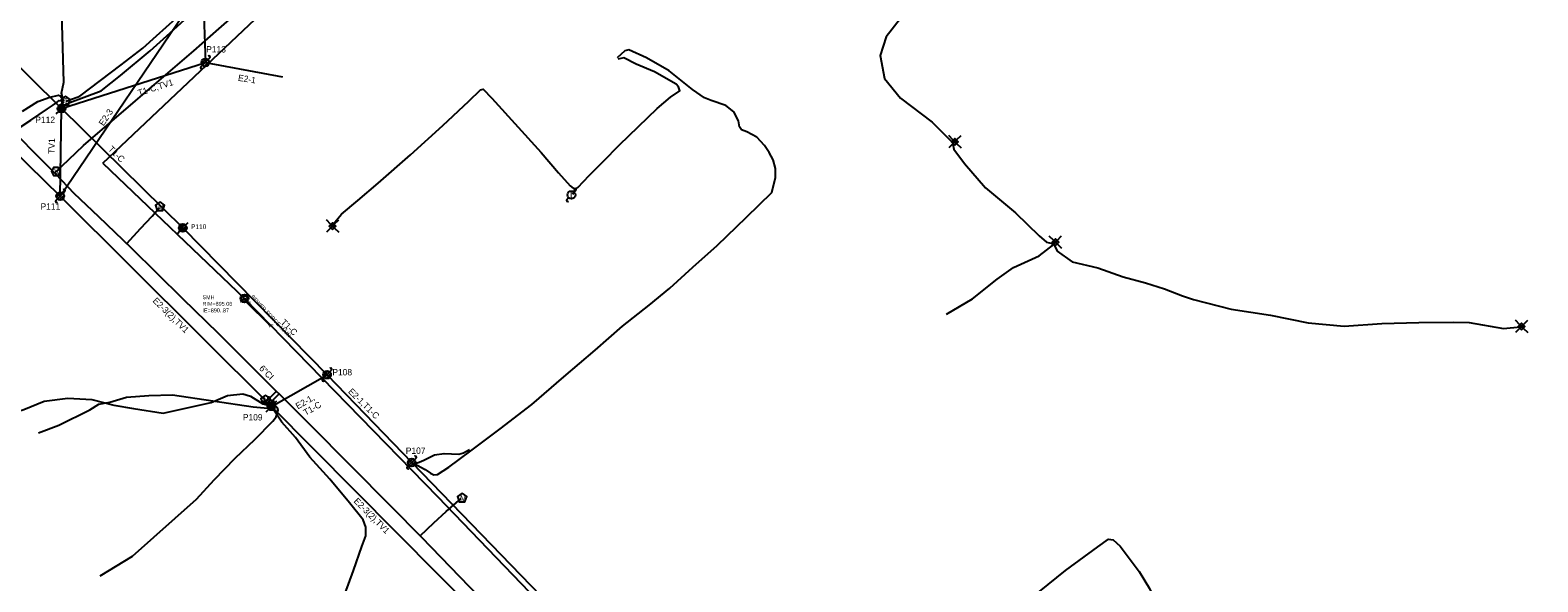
# Model space of a CAD drawing. Extents: x 1614474 to 1865144, y 1098877 to 1212550.
# Drawn here: x 1755426 to 1756381, y 1170044 to 1170393 of the extents above; entities that cross this region are included whole.
import ezdxf

# ---------------------------------------------------------------- set-up
doc = ezdxf.new("R2010")
doc.units = 0
for name, color, linetype in [('Default', 7, 'Continuous'), ('RD_EX_SU_Elec', 7, 'Continuous'), ('RD_EX_SU_H2O', 7, 'Continuous'), ('RD_EX_SU_Ovhd', 7, 'Continuous'), ('RD_EX_SU_Pole', 7, 'Continuous'), ('RD_EX_SU_Sewer', 7, 'Continuous'), ('RD_EX_SU_Telecom', 7, 'Continuous'), ('RD_EX_SU_TX_H2O', 7, 'Continuous'), ('RD_EX_SU_TX_Pole', 7, 'Continuous'), ('RD_EX_SU_TX_Sewer', 7, 'Continuous'), ('RD_EX_UT_txCode', 7, 'Continuous'), ('RD_SMD_Locator', 7, 'Continuous')]:
    doc.layers.add(name, color=color, linetype=linetype)

# ---------------------------------------------------------------- blocks, each defined once
blk = doc.blocks.new('SUE_PTP')
at = {"layer": 'RD_EX_SU_Pole'}
for p, q in [((-2.48, -0.33), (0.33, 2.48)), ((-2.1, -1.36), (1.36, 2.1)), ((-1.4, -2.08), (2.08, 1.4)), ((-0.38, -2.47), (2.47, 0.38)), ((1.77, 1.77), (3.42, 3.42)), ((-3.42, -3.42), (-1.77, -1.77)), ((1.52, -1.99), (1.99, -1.52))]:
    blk.add_line(p, q, dxfattribs=at)
blk.add_circle((0, 0), 2.5, dxfattribs=at)
blk = doc.blocks.new('SUE_SMH')
at = {"layer": 'RD_EX_SU_Sewer'}
blk.add_circle((0, 0), 2.5, dxfattribs=at)
blk.add_text('S', height=3.57, dxfattribs=at).set_placement((-1.1, -1.79))

msp = doc.modelspace()

# ---------------------------------------------------------------- linework, layer by layer
at = {"layer": 'Default'}
for p, q in [((1755562.03, 1170222.49), (1755560.63, 1170222.49)), ((1755561.33, 1170223.19), (1755561.33, 1170221.79))]:
    msp.add_line(p, q, dxfattribs=at)
at = {"layer": 'RD_EX_SU_Elec'}
msp.add_line((1755769.73, 1170288.79), (1755771.94, 1170292.51), dxfattribs=at)
for points in [[(1756017.8, 1170428.16), (1756008.58, 1170424.13), (1755977.33, 1170399.9), (1755968.08, 1170388.43), (1755964.43, 1170376.64), (1755967.1, 1170361.97), (1755977.19, 1170349.66), (1755997.36, 1170334.46), (1756009.95, 1170321.75)], [(1755669.02, 1170118.78), (1755676.38, 1170114.79), (1755679.78, 1170112.45), (1755681.75, 1170111.48), (1755684.09, 1170111.64), (1755691.34, 1170116.24), (1755705.15, 1170126.55), (1755723.71, 1170140.58), (1755743.76, 1170155.96), (1755764.15, 1170173.48), (1755783.87, 1170190.32), (1755801.35, 1170205.51), (1755818.14, 1170218.73), (1755831.29, 1170229.36), (1755845.85, 1170242.71), (1755861.2, 1170256.39), (1755879.67, 1170274.4), (1755895.87, 1170290.03), (1755898.13, 1170299.43), (1755898.05, 1170305.12), (1755896.64, 1170310.54), (1755894.02, 1170315.33), (1755891.25, 1170319.72), (1755886.27, 1170324.96), (1755879.88, 1170328.25), (1755876.6, 1170329.65), (1755875.38, 1170331.44), (1755874.71, 1170335.3), (1755871.77, 1170340.94), (1755866.63, 1170344.91), (1755857.41, 1170348.16), (1755853.09, 1170349.71), (1755845.62, 1170355.02), (1755830.83, 1170366.84), (1755816.52, 1170375.19), (1755805.26, 1170380.24), (1755802.74, 1170379.53), (1755797.92, 1170375.06)], [(1755618.1, 1170269.96), (1755623.39, 1170276.22), (1755633.75, 1170284.81), (1755646.57, 1170295.84), (1755666.96, 1170313.82), (1755687.48, 1170332.23), (1755703.98, 1170347.72), (1755711.25, 1170354.85), (1755713.07, 1170355.19), (1755718.51, 1170349.68), (1755749.77, 1170315.15), (1755760.69, 1170302.36), (1755768.14, 1170294.21), (1755770.98, 1170291.84), (1755772.95, 1170293.2), (1755780.25, 1170300.69), (1755789.11, 1170309.46), (1755799.38, 1170320.09), (1755823.12, 1170343.14), (1755831.66, 1170350.19), (1755837.58, 1170354.28), (1755836.65, 1170356.73), (1755835.13, 1170358.52), (1755821.44, 1170366.22), (1755809.99, 1170371.15), (1755802.05, 1170375.1), (1755798.27, 1170374.17)], [(1756010.36, 1170320.8), (1756011.01, 1170317.24), (1756017.76, 1170308.34), (1756030.98, 1170292.91), (1756050.1, 1170277.01), (1756065.02, 1170262.49), (1756069.77, 1170258.45), (1756073.45, 1170257.78)], [(1756006.39, 1170213.05), (1756022.78, 1170222.76), (1756038.42, 1170235.07), (1756048.77, 1170242.48), (1756065.02, 1170249.8), (1756074.27, 1170257.02)], [(1756074.51, 1170256.77), (1756076.39, 1170252.9), (1756085.89, 1170246.13), (1756102.17, 1170242.39), (1756118.29, 1170236.61), (1756132.4, 1170232.92), (1756144.33, 1170229.04), (1756155.71, 1170224.63), (1756162.64, 1170222.23), (1756186.51, 1170216.21), (1756211.5, 1170212.34), (1756235.26, 1170207.54), (1756258.17, 1170205.47), (1756281.96, 1170207.21), (1756305.43, 1170207.68), (1756327.12, 1170208.01), (1756337.21, 1170207.77), (1756359.06, 1170203.86), (1756369.7, 1170205.08)], [(1755431.62, 1170137.94), (1755444.3, 1170142.89), (1755464.09, 1170152.6), (1755469.74, 1170156.01), (1755476.6, 1170157.29), (1755487.21, 1170160.47), (1755501.41, 1170161.58), (1755516.41, 1170161.91), (1755567.36, 1170154.34), (1755576.72, 1170153.67), (1755579.12, 1170153.23)], [(1756022.72, 1169998.91), (1756038.36, 1170014.52), (1756054.32, 1170028.79), (1756081.79, 1170050.93), (1756102.19, 1170065.98), (1756109.03, 1170070.78), (1756111.93, 1170070.43), (1756116.38, 1170066.35), (1756128.3, 1170050.38), (1756134.86, 1170039.55), (1756137.29, 1170034.72), (1756139.43, 1170030.67), (1756144.81, 1170015.47), (1756151.96, 1169991.44), (1756159.74, 1169966.17), (1756168.64, 1169940.65), (1756178.37, 1169914.6), (1756188.01, 1169891.65), (1756198.92, 1169863.88), (1756203.62, 1169854.78), (1756207.42, 1169842.53)]]:
    msp.add_lwpolyline(points, dxfattribs=at)
at = {"layer": 'RD_EX_SU_H2O'}
for p, q in [((1755575.81, 1170158.11), (1755582.18, 1170164.3)), ((1755576.79, 1170160.62), (1755576.79, 1170159.29)), ((1755577.84, 1170160.62), (1755576.79, 1170160.62)), ((1755577.84, 1170159.26), (1755577.84, 1170160.62)), ((1755578.48, 1170157.26), (1755583.92, 1170162.62)), ((1755575.25, 1170157.84), (1755573.62, 1170157.84)), ((1755573.62, 1170157.84), (1755573.62, 1170156.79)), ((1755573.62, 1170156.79), (1755575.21, 1170156.79)), ((1755580.97, 1170157.84), (1755579.28, 1170157.84)), ((1755579.32, 1170156.79), (1755580.97, 1170156.79)), ((1755580.97, 1170156.79), (1755580.97, 1170157.84))]:
    msp.add_line(p, q, dxfattribs=at)
for points in [[(1755441.66, 1170302.24), (1755460.1, 1170319.63), (1755492.98, 1170347.81), (1755529.94, 1170379.56), (1755545.71, 1170393.41), (1755580.96, 1170424.36), (1755625.65, 1170470.71), (1755664.97, 1170520.56), (1755702.01, 1170579.47), (1755735.13, 1170631.62), (1755761.05, 1170675.7), (1755767.99, 1170686.69), (1755768.97, 1170688.48), (1755794.48, 1170732.14), (1755816.54, 1170772.41), (1755845.31, 1170822.63), (1755906.99, 1170918.56)], [(1755419.51, 1170324.82), (1755428.9, 1170315.01), (1755440.94, 1170302.99), (1755442.22, 1170301.65), (1755453.83, 1170289.61), (1755469.55, 1170274.72), (1755490.11, 1170254.98), (1755522.61, 1170222.9), (1755545.21, 1170201.07), (1755581.64, 1170164.83), (1755584.47, 1170162.08), (1755603.36, 1170143.23), (1755654.48, 1170091.61), (1755673.95, 1170071.98), (1755722.41, 1170022.15)], [(1755487.36, 1170257.63), (1755496.08, 1170267.09), (1755503.52, 1170274.97), (1755508.06, 1170280.36)], [(1755673.06, 1170072.88), (1755681.7, 1170080.98), (1755689.61, 1170088.29), (1755699.1, 1170096.4)]]:
    msp.add_lwpolyline(points, dxfattribs=at)
for points in [[(1755445.45, 1170303.25), (1755444.01, 1170305.75), (1755441.12, 1170305.75), (1755439.68, 1170303.25), (1755441.12, 1170300.75), (1755444.01, 1170300.75)], [(1755508.49, 1170284.08), (1755505.59, 1170281.98), (1755506.7, 1170278.57), (1755510.29, 1170278.57), (1755511.39, 1170281.98)], [(1755575.27, 1170161.77), (1755572.37, 1170159.67), (1755573.47, 1170156.26), (1755577.06, 1170156.26), (1755578.17, 1170159.67)], [(1755699.72, 1170099.88), (1755696.82, 1170097.78), (1755697.93, 1170094.37), (1755701.51, 1170094.37), (1755702.62, 1170097.78)]]:
    msp.add_lwpolyline(points, close=True, dxfattribs=at)
for radius in [2.1, 0.263]:
    msp.add_circle((1755577.27, 1170157.24), radius, dxfattribs=at)
for start, end in [(163.3387, 192.31502), (74.24552, 103.21276), (347.68498, 16.6613)]:
    msp.add_arc((1755577.27, 1170157.24), 2.1, start, end, dxfattribs=at)
at = {"layer": 'RD_EX_SU_Ovhd'}
for p, q in [((1755346.94, 1170440.97), (1755446.08, 1170343.01)), ((1755445.31, 1170287.7), (1755535.55, 1170420.8)), ((1755535.55, 1170420.8), (1755537.22, 1170372.19)), ((1755341.33, 1170388.64), (1755445.31, 1170287.7)), ((1755446.08, 1170343.01), (1755537.22, 1170372.19)), ((1755537.22, 1170372.19), (1755585.97, 1170363.18)), ((1755445.31, 1170287.7), (1755446.08, 1170343.01)), ((1755446.08, 1170343.01), (1755522.86, 1170267.55)), ((1755445.31, 1170287.7), (1755579.05, 1170154.72)), ((1755522.86, 1170267.55), (1755614.2, 1170174.75)), ((1755579.05, 1170154.72), (1755614.2, 1170174.75)), ((1755614.2, 1170174.75), (1755667.78, 1170119.23)), ((1755579.05, 1170154.72), (1755733.5, 1169999.29)), ((1755667.78, 1170119.23), (1755866.5, 1169914.45))]:
    msp.add_line(p, q, dxfattribs=at)
at = {"layer": 'RD_EX_SU_Pole'}
for p, q in [((1755534.39, 1170369.36), (1755535.45, 1170370.42)), ((1755534.81, 1170371.54), (1755537.87, 1170374.6)), ((1755535.45, 1170370.42), (1755538.99, 1170373.95)), ((1755536.57, 1170369.77), (1755539.64, 1170372.83)), ((1755538.99, 1170373.95), (1755540.05, 1170375.01)), ((1756010.66, 1170323.11), (1756007.83, 1170325.93)), ((1756012.75, 1170323.16), (1756015.59, 1170326)), ((1756010.61, 1170321), (1756007.78, 1170318.17)), ((1756012.78, 1170320.98), (1756015.61, 1170318.16)), ((1755442.48, 1170284.87), (1755443.54, 1170285.93)), ((1755442.89, 1170287.05), (1755445.96, 1170290.12)), ((1755443.54, 1170285.93), (1755447.08, 1170289.47)), ((1755444.66, 1170285.29), (1755447.72, 1170288.35)), ((1755447.08, 1170289.47), (1755448.14, 1170290.53)), ((1755766.08, 1170285.56), (1755767.14, 1170286.62)), ((1755770.68, 1170290.16), (1755771.74, 1170291.22)), ((1755519.44, 1170264.12), (1755521.1, 1170265.78)), ((1755520.38, 1170267.22), (1755523.2, 1170270.03)), ((1755520.77, 1170266.18), (1755524.23, 1170269.64)), ((1755521.47, 1170265.47), (1755524.94, 1170268.94)), ((1755522.49, 1170265.07), (1755525.34, 1170267.93)), ((1755524.39, 1170265.56), (1755524.85, 1170266.02)), ((1755524.63, 1170269.32), (1755526.29, 1170270.97)), ((1755616.59, 1170267.69), (1755613.76, 1170264.87)), ((1755616.64, 1170269.8), (1755613.81, 1170272.63)), ((1755618.72, 1170269.86), (1755621.56, 1170272.7)), ((1755618.76, 1170267.68), (1755621.59, 1170264.85)), ((1756074.19, 1170257.51), (1756071.37, 1170254.68)), ((1756074.24, 1170259.61), (1756071.42, 1170262.44)), ((1756076.33, 1170259.67), (1756079.17, 1170262.51)), ((1756076.37, 1170257.49), (1756079.19, 1170254.66)), ((1756369.43, 1170206.3), (1756366.6, 1170209.13)), ((1756371.51, 1170206.36), (1756374.35, 1170209.2)), ((1756369.37, 1170204.19), (1756366.55, 1170201.37)), ((1756371.55, 1170204.18), (1756374.37, 1170201.35)), ((1755611.37, 1170171.92), (1755612.43, 1170172.98)), ((1755611.79, 1170174.11), (1755614.85, 1170177.17)), ((1755612.43, 1170172.98), (1755615.97, 1170176.52)), ((1755613.56, 1170172.34), (1755616.62, 1170175.4)), ((1755615.97, 1170176.52), (1755617.03, 1170177.58)), ((1755669.55, 1170121), (1755670.61, 1170122.06)), ((1755664.95, 1170116.4), (1755666.01, 1170117.46)), ((1755665.36, 1170118.58), (1755668.43, 1170121.64)), ((1755666.01, 1170117.46), (1755669.55, 1170121)), ((1755667.13, 1170116.81), (1755670.19, 1170119.88))]:
    msp.add_line(p, q, dxfattribs=at)
for points in [[(1756011.72, 1170319.92), (1756013.84, 1170322.04), (1756011.72, 1170324.17), (1756009.6, 1170322.04)], [(1756011.72, 1170321.34), (1756012.43, 1170322.04), (1756011.72, 1170322.75), (1756011.02, 1170322.04)], [(1755617.7, 1170266.62), (1755619.82, 1170268.74), (1755617.7, 1170270.86), (1755615.58, 1170268.74)], [(1755617.7, 1170268.03), (1755618.41, 1170268.74), (1755617.7, 1170269.45), (1755616.99, 1170268.74)], [(1756075.31, 1170256.43), (1756077.43, 1170258.55), (1756075.31, 1170260.67), (1756073.18, 1170258.55)], [(1756075.31, 1170257.85), (1756076.01, 1170258.55), (1756075.31, 1170259.26), (1756074.6, 1170258.55)], [(1756370.49, 1170203.12), (1756372.61, 1170205.24), (1756370.49, 1170207.36), (1756368.36, 1170205.24)], [(1756370.49, 1170204.53), (1756371.19, 1170205.24), (1756370.49, 1170205.95), (1756369.78, 1170205.24)]]:
    msp.add_lwpolyline(points, close=True, dxfattribs=at)
for centre in [(1755537.22, 1170372.19), (1755445.31, 1170287.7), (1755768.91, 1170288.39), (1755522.86, 1170267.55), (1755614.2, 1170174.75), (1755667.78, 1170119.23)]:
    msp.add_circle(centre, 2.5, dxfattribs=at)
for centre, start, end in [((1755539.52, 1170375.54), 315, 135), ((1755534.92, 1170368.83), 135, 315), ((1755443.01, 1170284.34), 135, 315), ((1755447.61, 1170291.06), 315, 135), ((1755766.61, 1170285.03), 135, 315), ((1755771.21, 1170291.75), 315, 135), ((1755611.9, 1170171.39), 135, 315), ((1755616.5, 1170178.11), 315, 135), ((1755670.08, 1170122.59), 315, 135), ((1755665.48, 1170115.87), 135, 315)]:
    msp.add_arc(centre, 0.75, start, end, dxfattribs=at)
at = {"layer": 'RD_EX_SU_Sewer'}
msp.add_line((1755562.64, 1170221.23), (1755578.32, 1170205.72), dxfattribs=at)
for points in [[(1755472.28, 1170308.43), (1755611.28, 1170440.07), (1755685.92, 1170532.6), (1755771.11, 1170666.36), (1755900.75, 1170895.13), (1755970.93, 1170995.72), (1756034.36, 1171088.88), (1756090.2, 1171167.02), (1756147.55, 1171225.76), (1756231.9, 1171306.77), (1756311.52, 1171366.34), (1756443.61, 1171443.81), (1756596.95, 1171527.35), (1756716.89, 1171571.4), (1756861.63, 1171600.26), (1756930.46, 1171628.36), (1757060.01, 1171710.39), (1757108.59, 1171767.1), (1757159.2, 1171859.25), (1757206.77, 1171953.42), (1757250.3, 1172017.89), (1757282.69, 1172067.18)], [(1755472.28, 1170308.43), (1755562.01, 1170223), (1755684.15, 1170097.75), (1755848.2, 1169927.49), (1755891.42, 1169870.58), (1755920.4, 1169827.47), (1756045.49, 1169608.65)]]:
    msp.add_lwpolyline(points, dxfattribs=at)
msp.add_circle((1755561.8, 1170222.9), 2, dxfattribs=at)
at = {"layer": 'RD_EX_SU_Telecom'}
for p, q in [((1755443.6, 1170342.68), (1755446.41, 1170345.49)), ((1755443.99, 1170341.65), (1755447.45, 1170345.11)), ((1755444.69, 1170340.93), (1755448.16, 1170344.41)), ((1755445.7, 1170340.54), (1755448.56, 1170343.39)), ((1755447.61, 1170341.02), (1755448.07, 1170341.49)), ((1755447.85, 1170344.78), (1755449.51, 1170346.43)), ((1755442.66, 1170339.59), (1755444.31, 1170341.24))]:
    msp.add_line(p, q, dxfattribs=at)
for points in [[(1755449.11, 1170347.65), (1755457.73, 1170350.8), (1755483.9, 1170370.75), (1755497.68, 1170381.21), (1755506.16, 1170389.1), (1755530.61, 1170411.02), (1755547.76, 1170427.26), (1755566.03, 1170443.65), (1755574.14, 1170451.88), (1755595.4, 1170477.57), (1755625.82, 1170514.33), (1755650.49, 1170549.56), (1755673.65, 1170585.08), (1755694.99, 1170619), (1755717.26, 1170654.88), (1755742.17, 1170695.76), (1755765.78, 1170735.4), (1755785.74, 1170774.51), (1755802.58, 1170805.04), (1755825.12, 1170841.06), (1755847.25, 1170877.87), (1755862.45, 1170898.72), (1755872.49, 1170915.51)], [(1755445.25, 1170344.06), (1755446.67, 1170346.87), (1755446.7, 1170350.47), (1755446.14, 1170352.74), (1755447.49, 1170359.74), (1755446.59, 1170396.26), (1755446.48, 1170419.76)], [(1755446.79, 1170344.44), (1755451.4, 1170346.81), (1755460.49, 1170350.22), (1755471.27, 1170354.25), (1755483.52, 1170363.87), (1755502.25, 1170379.57), (1755514.96, 1170391), (1755542.24, 1170415.97)], [(1755421.33, 1170341.29), (1755431, 1170347.4), (1755438.64, 1170350.17), (1755442.41, 1170351.15), (1755444.23, 1170351.54), (1755445.28, 1170351), (1755446.51, 1170349.43), (1755447.78, 1170348.08)], [(1755416.15, 1170328.72), (1755426.62, 1170335.77), (1755437.27, 1170342.91), (1755440.35, 1170345.05), (1755442.42, 1170346.51), (1755444.68, 1170348.06), (1755447.73, 1170347.81)], [(1755447.47, 1170347.06), (1755446.12, 1170345.44), (1755445.81, 1170344.48)], [(1755405.67, 1170145.67), (1755405.69, 1170145.88), (1755409.29, 1170148.79), (1755412.83, 1170149.69), (1755422.25, 1170152.84), (1755435.11, 1170158.07), (1755450.17, 1170159.81), (1755465.33, 1170159.04), (1755479.15, 1170155.53), (1755491.77, 1170153.46), (1755510.49, 1170150.43), (1755540.94, 1170157.22), (1755551.15, 1170161.61), (1755560.81, 1170162.66), (1755565.75, 1170161.22), (1755573.61, 1170156.42), (1755577.72, 1170155.21)], [(1755470.54, 1170047.64), (1755490.99, 1170059.96), (1755531.52, 1170096.01), (1755542.79, 1170108.34), (1755556.11, 1170121.99), (1755568.55, 1170133.76), (1755579.85, 1170145.26), (1755581.95, 1170148.05), (1755583.22, 1170152.4), (1755582.81, 1170153.87), (1755580.89, 1170155.73)], [(1755567.85, 1169924.8), (1755569.62, 1169926.81), (1755568.28, 1169954.57), (1755566.99, 1169976.86), (1755565.52, 1169986.95), (1755567.37, 1169988.76), (1755569.56, 1169989.18), (1755580.03, 1169990.8), (1755593.08, 1169994.88), (1755603.19, 1170003.52), (1755613.47, 1170014.77), (1755617.97, 1170022.17), (1755625.55, 1170035.96), (1755631.01, 1170050.95), (1755636.29, 1170066.08), (1755638.75, 1170072.83), (1755638.78, 1170078.26), (1755637.07, 1170082.95), (1755628.43, 1170093.71), (1755615.86, 1170108.75), (1755603.37, 1170122.6), (1755594.17, 1170134.98), (1755585.49, 1170144.68), (1755579.2, 1170154.15)], [(1755668.73, 1170118.16), (1755672.42, 1170119.44), (1755675.57, 1170120.66), (1755682.15, 1170124.06), (1755688.29, 1170124.88), (1755697.61, 1170124.58), (1755700.68, 1170125.41), (1755704.42, 1170127.39)]]:
    msp.add_lwpolyline(points, dxfattribs=at)
msp.add_lwpolyline([(1755448.64, 1170350.83), (1755445.79, 1170348.76), (1755446.88, 1170345.41), (1755450.41, 1170345.41), (1755451.49, 1170348.76)], close=True, dxfattribs=at)
msp.add_circle((1755446.08, 1170343.01), 2.5, dxfattribs=at)
at = {"layer": 'RD_SMD_Locator'}
for centre in [(1755562.64, 1170221.23), (1755578.32, 1170205.72)]:
    msp.add_circle(centre, 0.001, dxfattribs=at)

# ---------------------------------------------------------------- block references
at = {"layer": 'RD_EX_SU_Sewer'}
msp.add_blockref('SUE_SMH', (1755561.91, 1170223), dxfattribs=at)
at = {"layer": 'RD_EX_SU_Telecom'}
msp.add_blockref('SUE_PTP', (1755579.05, 1170154.72), dxfattribs=at)

# ---------------------------------------------------------------- texts
at = {"layer": 'Default'}
msp.add_text('17055', height=1, dxfattribs=at).set_placement((1755559.5, 1170224.69))
at = {"layer": 'RD_EX_SU_H2O'}
for s, p in [('V', (1755441.36, 1170301.37)), ('M', (1755507.12, 1170279.04)), ('M', (1755573.9, 1170156.73)), ('M', (1755698.35, 1170094.84))]:
    msp.add_text(s, height=3.75, dxfattribs=at).set_placement(p)
at = {"layer": 'RD_EX_SU_Ovhd'}
for s, rotation, p in [('T1-C,TV1', 17.75179, (1755495.15, 1170350.89)), ('E2-1', 351.26625, (1755557.63, 1170360.6)), ('E2-3', 55.86348, (1755472.66, 1170331.68)), ('TV1', 89.19759, (1755441.79, 1170314.38)), ('T1-C', 315.60508, (1755475.26, 1170316.95)), ('E2-3(2),TV1', 315.55161, (1755503.53, 1170221.12)), ('T1-C', 315.60508, (1755584.55, 1170207.46)), ('E2-1,', 29.78213, (1755595.7, 1170152.76)), ('E2-1,T1-C', 315.60508, (1755627.27, 1170163.66)), ('T1-C', 29.78213, (1755600.67, 1170148.69)), ('E2-3(2),TV1', 314.95685, (1755630.81, 1170094.45))]:
    msp.add_text(s, height=4, rotation=rotation, dxfattribs=at).set_placement(p)
at = {"layer": 'RD_EX_SU_Pole'}
msp.add_text('L', height=4, dxfattribs=at).set_placement((1755768.05, 1170286.39))
at = {"layer": 'RD_EX_SU_Sewer'}
msp.add_text('S', height=2.5, dxfattribs=at).set_placement((1755560.78, 1170221.71))
at = {"layer": 'RD_EX_SU_Telecom'}
msp.add_text('T', height=3.75, dxfattribs=at).set_placement((1755447.39, 1170345.96))
at = {"layer": 'RD_EX_SU_TX_H2O'}
msp.add_text('6"CI', height=4, rotation=315.15246, dxfattribs=at).set_placement((1755570.88, 1170178.35))
at = {"layer": 'RD_EX_SU_TX_Pole'}
for s, height, p in [('P113', 4, (1755537.68, 1170378.47)), ('P112', 4, (1755429.51, 1170333.94)), ('P111', 4, (1755432.81, 1170279.1)), ('P110', 3, (1755528.09, 1170266.81)), ('P108', 4, (1755617.56, 1170174.32)), ('P109', 4, (1755560.88, 1170145.81)), ('P107', 4, (1755664.05, 1170124.71))]:
    msp.add_text(s, height=height, dxfattribs=at).set_placement(p)
at = {"layer": 'RD_EX_SU_TX_Sewer'}
for s, p in [('SMH', (1755535.3, 1170222.48)), ('RIM=895.06', (1755535.3, 1170218.31)), ('IE=890..87', (1755535.3, 1170214.14))]:
    msp.add_text(s, height=2.5, dxfattribs=at).set_placement(p)
msp.add_text('SEWER FORCE MAIN', height=2.5, rotation=313.3752, dxfattribs=at).set_placement((1755565.58, 1170223.8))
at = {"layer": 'RD_EX_UT_txCode'}
for s, p in [('BL*FSS 6IN', (1755558.5, 1170220.23)), ('17053', (1755559.97, 1170223.9)), ('SMH', (1755560.51, 1170220.9)), ('17054', (1755560.81, 1170221.23)), ('17056', (1755576.46, 1170205.72)), ('6IN', (1755577.37, 1170204.72))]:
    msp.add_text(s, height=1, dxfattribs=at).set_placement(p)

doc.saveas('drawing.dxf')
